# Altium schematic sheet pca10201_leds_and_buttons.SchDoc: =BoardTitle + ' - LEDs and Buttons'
size A3; Organization: Nordic Semiconductor; DocumentNumber: 4; SheetNumber: 4; SheetTotal: 10; CompanyName: Nordic Semiconductor; DocumentSize: A3
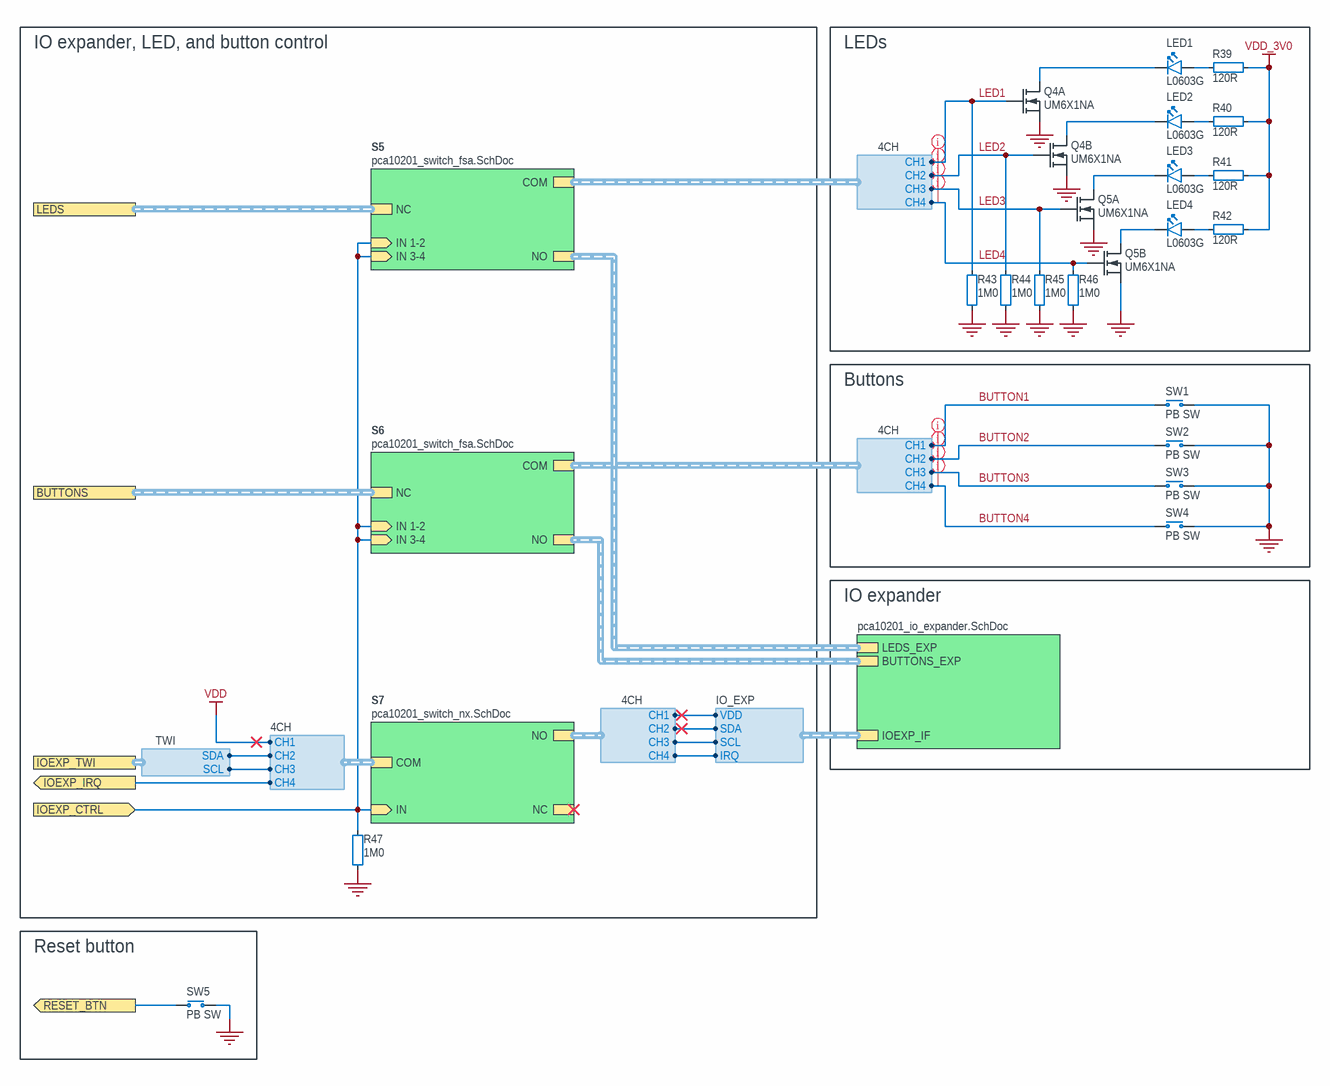
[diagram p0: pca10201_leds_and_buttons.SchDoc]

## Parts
LED1  L0603G  [LED_0603_G]
LED2  L0603G  [LED_0603_G]
LED3  L0603G  [LED_0603_G]
LED4  L0603G  [LED_0603_G]
Q4  UM6X1NA  [SOTFL50P162X60-6N]  (parts A,B of 2)
Q5  UM6X1NA  [SOTFL50P162X60-6N]  (parts A,B of 2)
R39  120R  [RESC0603X03L_C]
R40  120R  [RESC0603X03L_C]
R41  120R  [RESC0603X03L_C]
R42  120R  [RESC0603X03L_C]
R43  1M0  [RESC0603X03L_C]
R44  1M0  [RESC0603X03L_C]
R45  1M0  [RESC0603X03L_C]
R46  1M0  [RESC0603X03L_C]
R47  1M0  [RESC0603X03L_C]
SW1  PB SW  [L-KLS7-TS6616B-2.5-160-T]
SW2  PB SW  [L-KLS7-TS6616B-2.5-160-T]
SW3  PB SW  [L-KLS7-TS6616B-2.5-160-T]
SW4  PB SW  [L-KLS7-TS6616B-2.5-160-T]
SW5  PB SW  [L-KLS7-TS6616B-2.5-160-T]

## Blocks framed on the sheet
IO expander, LED, and button control: R47
LEDs: LED1-LED4 Q4 Q5 R39-R46
Buttons: SW1-SW4
Reset button: SW5

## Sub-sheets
Designator = pca10201_io_expander.SchDoc: LEDS_EXP (harness 4CH), BUTTONS_EXP (harness 4CH), IOEXP_IF (harness IO_EXP)
S5 = pca10201_switch_fsa.SchDoc: IN 1-2 (in), COM (harness 4CH), NC (harness 4CH), NO (harness 4CH), IN 3-4 (in)
S6 = pca10201_switch_fsa.SchDoc: IN 1-2 (in), COM (harness 4CH), NC (harness 4CH), NO (harness 4CH), IN 3-4 (in)
S7 = pca10201_switch_nx.SchDoc: IN (in), COM (harness 4CH), NC (harness 4CH), NO (harness 4CH)

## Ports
BUTTONS (harness 4CH), IOEXP_CTRL (in), IOEXP_IRQ (out), IOEXP_TWI (harness TWI), LEDS (harness 4CH), RESET_BTN (out)

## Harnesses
4CH: CH1, CH2, CH3, CH4
IO_EXP: VDD, SCL, SDA, IRQ
TWI: SCL, SDA

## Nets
GND: Q4.1(S1) Q4.4(S2) Q5.1(S1) Q5.4(S2) R43.1 R44.1 R45.1 R46.1 R47.1 SW1.1(N.O) SW2.1(N.O) SW3.1(N.O) SW4.1(N.O) SW5.1(N.O)
VDD_3V0: R39.2 R40.2 R41.2 R42.2
BUTTON1: SW1.2(COM) ; sheet S6/COM.CH1
BUTTON2: SW2.2(COM) ; sheet S6/COM.CH2
BUTTON3: SW3.2(COM) ; sheet S6/COM.CH3
BUTTON4: SW4.2(COM) ; sheet S6/COM.CH4
IOEXP_CTRL: R47.2 ; port IOEXP_CTRL, sheet S5/IN 1-2, sheet S5/IN 3-4, sheet S6/IN 1-2, sheet S6/IN 3-4, sheet S7/IN
IOEXP_IRQ: port IOEXP_IRQ, sheet S7/COM.CH4
LED1: Q4.2(G1) R43.2 ; sheet S5/COM.CH1
LED2: Q4.5(G2) R44.2 ; sheet S5/COM.CH2
LED3: Q5.2(G1) R45.2 ; sheet S5/COM.CH3
LED4: Q5.5(G2) R46.2 ; sheet S5/COM.CH4
RESET_BTN: SW5.2(COM) ; port RESET_BTN
NetLED1_1: LED1.1(C) Q4.6(D1)
NetLED1_2: LED1.2(A) R39.1
NetLED2_1: LED2.1(C) Q4.3(D2)
NetLED2_2: LED2.2(A) R40.1
NetLED3_1: LED3.1(C) Q5.6(D1)
NetLED3_2: LED3.2(A) R41.1
NetLED4_1: LED4.1(C) Q5.3(D2)
NetLED4_2: LED4.2(A) R42.1
(unnamed): sheet S7/NO.CH1, sheet Designator/IOEXP_IF.VDD
(unnamed): sheet S7/NO.CH2, sheet Designator/IOEXP_IF.SDA  [a separate net that carries the same name]
(unnamed): sheet S7/NO.CH3, sheet Designator/IOEXP_IF.SCL  [a separate net that carries the same name]
(unnamed): sheet S7/NO.CH4, sheet Designator/IOEXP_IF.IRQ  [a separate net that carries the same name]
(unnamed): sheet S7/COM.CH2, port IOEXP_TWI.SDA  [a separate net that carries the same name]
(unnamed): sheet S7/COM.CH3, port IOEXP_TWI.SCL  [a separate net that carries the same name]

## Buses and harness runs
harness port BUTTONS = sheet S6/NC
harness port LEDS = sheet S5/NC
harness sheet Designator/BUTTONS_EXP = sheet S6/NO
harness sheet Designator/LEDS_EXP = sheet S5/NO

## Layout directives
net class GPIO: BUTTON1, BUTTON2, BUTTON3, BUTTON4, LED1, LED2, LED3, LED4

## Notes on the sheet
- IO expander

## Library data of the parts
LED1-LED4 = VS 25C7M5: LED, Green, 0603, 573nm, Vf=2.0V, 24mcd, - 40 to +85°C; Manufacturer: Victory Electronics; Part number IPS: 00000001274, 00000009961; Part number Norautron: 26313411; Part number NEMS: 101400097; Note: N.A.; Artikkelnr Noca: 13019193; Pad Count: 2; Component Status: Active
Q4 Q5 = UM6X1NA: Dual N-Channel MOSFET, Vds = 30V, Vgs(th) = 1.5V, Id = 0.5A, Rds = 750mOhm, Pd = 150mW, -55°C ~ 150°C; Manufacturer: Micro Commercial Components; Manufacturer Part Number: UM6X1NA-TP; Part number NEMS: 101300201; Note: N.A.; Pad Count: 6; Component Status: Active
R39-R42 = R0201-120: Resistor, ±1%, 0.05W; Manufacturer: N.A.; Part number IPS: 00000000880; Part number Norautron: 26107076; Part number NEMS: 100100028; Note: Chip Res 1%; Pad Count: 2; Component Status: Active
R43-R47 = R0201-1M0: Resistor, ±1%, 0.05W; Manufacturer: N.A.; Part number IPS: 00000001418; Part number Norautron: 26107108; Part number NEMS: 100100093; Note: Chip Res 1%; Pad Count: 2; Component Status: Active
SW1-SW5 = L-KLS7-TS6616B-2.5-160-T: Tactile Switch, SPNO, SMD, 160gf, 6.2x6.4x2.5mm; Manufacturer: KLS; Part number NEMS: 101500133, 101500001; Note: N.A.; Pad Count: 4; Component Status: Active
